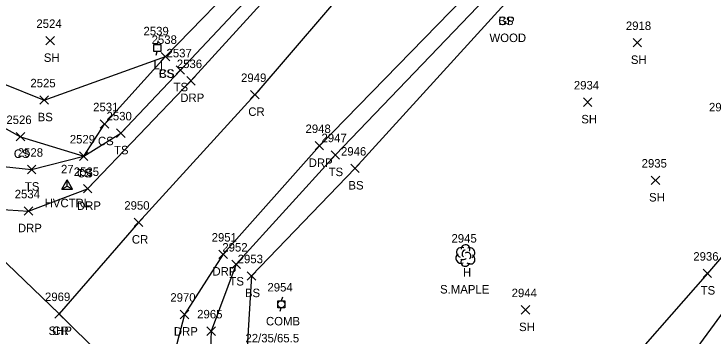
# Model space of a CAD drawing. Extents: x 1472233 to 1475777, y 540726 to 543442.
# Drawn here: x 1473841.3 to 1474005.9, y 542446.8 to 542522.7 of the extents above; entities that cross this region are included whole.
import ezdxf

# ---------------------------------------------------------------- set-up
doc = ezdxf.new("R2010")
doc.units = 0
for name, color, linetype in [('C_A', 7, 'Continuous'), ('C_I', 7, 'Continuous'), ('CPSM', 7, 'Continuous'), ('L_A', 7, 'Continuous'), ('L_C', 7, 'Continuous'), ('L_I', 7, 'Continuous'), ('L_TIC', 7, 'Continuous'), ('LELB', 7, 'Continuous'), ('LTD', 7, 'Continuous'), ('P_A', 7, 'Continuous'), ('P_I', 7, 'Continuous'), ('P_TIC', 7, 'Continuous'), ('PRC', 7, 'Continuous'), ('PSP', 7, 'Continuous'), ('R_A', 7, 'Continuous'), ('R_C', 7, 'Continuous'), ('R_I', 7, 'Continuous'), ('R_TIC', 7, 'Continuous'), ('RDP', 7, 'Continuous'), ('U_A', 7, 'Continuous'), ('U_C', 7, 'Continuous'), ('U_I', 7, 'Continuous'), ('ULP', 7, 'Continuous'), ('UP', 7, 'Continuous')]:
    doc.layers.add(name, color=color, linetype=linetype)

msp = doc.modelspace()

# ---------------------------------------------------------------- linework, layer by layer
at = {"layer": 'CPSM'}
for p, q in [((1473852.58, 542481.43), (1473853.83, 542483.59)), ((1473855.08, 542481.43), (1473853.83, 542483.59)), ((1473853.83, 542482.15), (1473853.83, 542483.59)), ((1473852.58, 542481.43), (1473853.83, 542482.15)), ((1473852.58, 542481.43), (1473855.08, 542481.43)), ((1473853.83, 542482.15), (1473853.83, 542482.15)), ((1473853.83, 542482.15), (1473855.08, 542481.43))]:
    msp.add_line(p, q, dxfattribs=at)
at = {"layer": 'L_TIC'}
for points in [[(1473848.84, 542515.42), (1473850.84, 542517.42)], [(1473850.84, 542515.42), (1473848.84, 542517.42)], [(1473987.03, 542514.93), (1473989.03, 542516.93)], [(1473989.03, 542514.93), (1473987.03, 542516.93)], [(1473875.97, 542511.66), (1473877.97, 542513.66)], [(1473877.97, 542511.66), (1473875.97, 542513.66)], [(1473875.97, 542511.66), (1473877.97, 542513.66)], [(1473877.97, 542511.66), (1473875.97, 542513.66)], [(1473879.47, 542508.49), (1473881.47, 542510.49)], [(1473881.47, 542508.49), (1473879.47, 542510.49)], [(1473847.43, 542501.42), (1473849.43, 542503.42)], [(1473849.43, 542501.42), (1473847.43, 542503.42)], [(1473975.36, 542500.92), (1473977.36, 542502.92)], [(1473977.36, 542500.92), (1473975.36, 542502.92)], [(1473861.63, 542495.77), (1473863.63, 542497.77)], [(1473863.63, 542495.77), (1473861.63, 542497.77)], [(1473865.44, 542493.63), (1473867.44, 542495.63)], [(1473867.44, 542493.63), (1473865.44, 542495.63)], [(1473841.83, 542492.77), (1473843.83, 542494.77)], [(1473843.83, 542492.77), (1473841.83, 542494.77)], [(1473856.71, 542488.19), (1473858.71, 542490.19)], [(1473858.71, 542488.19), (1473856.71, 542490.19)], [(1473856.71, 542488.19), (1473858.71, 542490.19)], [(1473858.71, 542488.19), (1473856.71, 542490.19)], [(1473915.95, 542488.49), (1473917.95, 542490.49)], [(1473917.95, 542488.49), (1473915.95, 542490.49)], [(1473920.59, 542485.33), (1473922.59, 542487.33)], [(1473922.59, 542485.33), (1473920.59, 542487.33)], [(1473844.46, 542485.06), (1473846.46, 542487.06)], [(1473846.46, 542485.06), (1473844.46, 542487.06)], [(1473991.31, 542482.51), (1473993.31, 542484.51)], [(1473993.31, 542482.51), (1473991.31, 542484.51)], [(1473892.61, 542462.71), (1473894.61, 542464.71)], [(1473894.61, 542462.71), (1473892.61, 542464.71)], [(1473896.23, 542459.96), (1473898.23, 542461.96)], [(1473898.23, 542459.96), (1473896.23, 542461.96)], [(1474003.53, 542460.57), (1474005.53, 542462.57)], [(1474005.53, 542460.57), (1474003.53, 542462.57)], [(1473960.71, 542451.96), (1473962.71, 542453.96)], [(1473962.71, 542451.96), (1473960.71, 542453.96)], [(1473886.74, 542446.96), (1473888.74, 542448.96)], [(1473888.74, 542446.96), (1473886.74, 542448.96)]]:
    msp.add_lwpolyline(points, dxfattribs=at)
at = {"layer": 'LELB'}
for points in [[(1473518.4, 542790.01), (1473563.89, 542744.47), (1473596.86, 542712.19), (1473621.23, 542688.95), (1473660.33, 542651.88), (1473689.02, 542624.42), (1473715.73, 542598.61), (1473746.44, 542571.32), (1473784.75, 542534.69), (1473817.99, 542514.69), (1473848.43, 542502.42), (1473876.97, 542512.66), (1473897.43, 542533.79), (1473923.6, 542558.96), (1473938.44, 542588.81), (1473927.53, 542599.64)], [(1473514.27, 542786.32), (1473560.24, 542740.99), (1473594.17, 542708.93), (1473617.93, 542685.84), (1473656.3, 542648.39), (1473686.09, 542620.25), (1473711.9, 542594.5), (1473742.08, 542567.84), (1473780.05, 542529.89), (1473807.97, 542506.72), (1473829.24, 542487.77), (1473845.46, 542486.06), (1473857.71, 542489.19), (1473866.44, 542494.63), (1473880.47, 542509.49), (1473900.34, 542530.71), (1473925.82, 542557.03), (1473946.47, 542580.98), (1473946.59, 542594.08), (1473931.4, 542613.43), (1473912.61, 542619.34)], [(1474165.95, 542731.94), (1474157.14, 542683.61), (1474148.57, 542649.89), (1474143.29, 542635.5), (1474139.19, 542631.93), (1474131.36, 542636.12), (1474120.53, 542648.69), (1474108.56, 542670.06), (1474101.39, 542688.23), (1474095.89, 542684.64), (1474093.95, 542684.48), (1474093.45, 542683.67), (1474093.16, 542677.96), (1474112.56, 542649.15), (1474130.63, 542628.83), (1474135.77, 542616.46), (1474134.45, 542606.68), (1474129.24, 542593.89), (1474099.76, 542548.63), (1474087.76, 542535.06), (1474054.57, 542501.68), (1474028.74, 542469.85), (1474011.69, 542457.24), (1473991.56, 542429.6)], [(1474090.14, 542675.56), (1474109.18, 542645.42), (1474125.12, 542625.07), (1474129.54, 542610.53), (1474116.17, 542580.79), (1474095.87, 542551.75), (1474082.52, 542541.7), (1474047.4, 542508.8), (1474023.57, 542483.66), (1474004.53, 542461.57), (1473981.42, 542435.1), (1473957.61, 542405.93), (1473949.71, 542379.54)], [(1474011.53, 542544.93), (1473997.92, 542550.92), (1473986.64, 542551.14), (1473974.36, 542545.99), (1473954.07, 542528.34), (1473916.95, 542489.49), (1473893.61, 542463.71), (1473887.74, 542447.96), (1473887.15, 542433.61)], [(1474038.07, 542519.87), (1474008.75, 542541.19), (1473994.7, 542544.04), (1473978.76, 542543.22), (1473956.88, 542525.09), (1473921.59, 542486.33), (1473897.23, 542460.96), (1473895.8, 542437.81), (1473900.03, 542423.77), (1473906.31, 542415.11), (1473930.79, 542395.25), (1473949.71, 542379.54), (1473992.28, 542347.15), (1474032.15, 542310.9), (1474067.46, 542281.43), (1474108.17, 542240.59), (1474125.43, 542226.08)], [(1473784.75, 542534.69), (1473812.87, 542510.45), (1473842.83, 542493.77), (1473857.71, 542489.19), (1473862.63, 542496.77), (1473876.97, 542512.66)]]:
    msp.add_lwpolyline(points, dxfattribs=at)
at = {"layer": 'LTD'}
msp.add_line((1473947.55, 542465.82), (1473947.55, 542465.82), dxfattribs=at)
msp.add_line((1473947.55, 542465.82), (1473947.55, 542465.82), dxfattribs=at)
msp.add_arc((1473947.59, 542467.26), 1.05, 335.5272, 180.9563, dxfattribs=at)
for centre, major_axis, ratio, start_param, end_param in [((1473946.76, 542466.49), (1.21, -0.51), 0.895232, 1.570796, 4.712389), ((1473948.59, 542466.41), (-1.14, -0.48), 0.949671, 1.570796, 4.712389), ((1473946.46, 542465.12), (0.58, -1.04), 0.959034, 3.141593, 6.283185), ((1473947.34, 542466.28), (-0.208, -0.792), 0.645439, 3.141593, 6.283185), ((1473948.05, 542465.66), (-0.5, 0.667), 0.989748, 3.141593, 6.283185), ((1473947.55, 542464.32), (0.26, 1.06), 0.942809, 1.570796, 4.712389), ((1473947.09, 542465.07), (-0.625, -0.083), 0.423636, 0, 3.141593), ((1473948.55, 542464.99), (-1.09, 0.79), 0.841452, 1.570796, 4.712389)]:
    msp.add_ellipse(centre, major_axis=major_axis, ratio=ratio, start_param=start_param, end_param=end_param, dxfattribs=at)
at = {"layer": 'P_TIC'}
for points in [[(1473897.02, 542502.68), (1473899.02, 542504.68)], [(1473899.02, 542502.68), (1473897.02, 542504.68)], [(1473869.62, 542472.58), (1473871.62, 542474.58)], [(1473871.62, 542472.58), (1473869.62, 542474.58)], [(1473850.91, 542451.04), (1473852.91, 542453.04)], [(1473852.91, 542451.04), (1473850.91, 542453.04)], [(1473850.91, 542451.04), (1473852.91, 542453.04)], [(1473852.91, 542451.04), (1473850.91, 542453.04)]]:
    msp.add_lwpolyline(points, dxfattribs=at)
at = {"layer": 'PRC'}
msp.add_lwpolyline([(1474124.73, 542867.45), (1474138.24, 542842.57), (1474146.26, 542814.27), (1474147.99, 542793.2), (1474140.2, 542767.69), (1474131.39, 542751.59), (1474113.96, 542729.51), (1474092.05, 542706.63), (1474043.97, 542656.44), (1473995.22, 542610.58), (1473969.45, 542582.1), (1473923.18, 542533.15), (1473898.02, 542503.68), (1473870.62, 542473.58), (1473851.91, 542452.04)], dxfattribs=at)
at = {"layer": 'PSP'}
msp.add_lwpolyline([(1473511.53, 542783.65), (1473557.71, 542738.52), (1473591.71, 542705.85), (1473614.8, 542682.52), (1473653.25, 542645.69), (1473682.39, 542616.78), (1473708.77, 542591.71), (1473737.42, 542563.39), (1473776.1, 542525.9), (1473801.03, 542501.12), (1473821.16, 542481.55), (1473851.91, 542452.04), (1473882.06, 542422.12), (1473920.54, 542384.18), (1473958.97, 542346.58), (1473974.8, 542332.02), (1474016, 542291.37), (1474048.58, 542260.06), (1474087.68, 542221.94), (1474123.03, 542187.8), (1474161.37, 542151.41), (1474230.43, 542083.96), (1474265.44, 542049.86)], dxfattribs=at)
at = {"layer": 'R_TIC'}
for points in [[(1473881.96, 542505.96), (1473883.96, 542507.96)], [(1473883.96, 542505.96), (1473881.96, 542507.96)], [(1473912.19, 542490.65), (1473914.19, 542492.65)], [(1473914.19, 542490.65), (1473912.19, 542492.65)], [(1473857.64, 542480.53), (1473859.64, 542482.53)], [(1473859.64, 542480.53), (1473857.64, 542482.53)], [(1473843.74, 542475.26), (1473845.74, 542477.26)], [(1473845.74, 542475.26), (1473843.74, 542477.26)], [(1473889.53, 542465.06), (1473891.53, 542467.06)], [(1473891.53, 542465.06), (1473889.53, 542467.06)], [(1473880.45, 542450.89), (1473882.45, 542452.89)], [(1473882.45, 542450.89), (1473880.45, 542452.89)]]:
    msp.add_lwpolyline(points, dxfattribs=at)
at = {"layer": 'RDP'}
for points in [[(1474156.9, 542816.07), (1474158.25, 542792.55), (1474149.71, 542763.53), (1474141.06, 542745.97), (1474122.05, 542721.57), (1474099.16, 542696.92), (1474072.3, 542669.38), (1474064.97, 542659.15), (1474064.16, 542645.99), (1474070.96, 542633.45), (1474104.89, 542594.5), (1474067.57, 542556.96), (1474038.11, 542526.02), (1474001.11, 542557.22), (1473988.17, 542557.88), (1473978.19, 542554.56), (1473968.9, 542548.06), (1473950.18, 542529.64), (1473913.19, 542491.65), (1473890.53, 542466.06), (1473881.45, 542451.89), (1473878.79, 542441.67), (1473879.57, 542429.36), (1473882.06, 542422.12)], [(1473821.16, 542481.55), (1473834.93, 542476.88), (1473844.74, 542476.26), (1473858.64, 542481.53), (1473882.96, 542506.96), (1473902.65, 542528.64), (1473928.15, 542555.41), (1473950.59, 542578.52), (1473956.71, 542587.39), (1473958.08, 542597.85), (1473945.85, 542612.63), (1473922.1, 542634.86), (1473922.68, 542635.63), (1473934.21, 542647.92)]]:
    msp.add_lwpolyline(points, dxfattribs=at)
at = {"layer": 'ULP'}
for p, q in [((1473874.22, 542513.85), (1473874.22, 542515.51)), ((1473874.22, 542515.51), (1473875.89, 542515.51)), ((1473875.22, 542516.35), (1473875.05, 542515.51)), ((1473875.89, 542515.51), (1473875.89, 542513.85)), ((1473875.89, 542513.85), (1473874.22, 542513.85)), ((1473874.8, 542513.01), (1473875.05, 542513.85)), ((1473875.05, 542514.68), (1473875.05, 542514.68))]:
    msp.add_line(p, q, dxfattribs=at)
at = {"layer": 'UP'}
for p, q in [((1473903.4, 542453.47), (1473903.4, 542455.13)), ((1473903.4, 542455.13), (1473905.07, 542455.13)), ((1473904.48, 542455.97), (1473904.23, 542455.13)), ((1473905.07, 542455.13), (1473905.07, 542453.47)), ((1473905.07, 542453.47), (1473903.4, 542453.47)), ((1473903.98, 542452.63), (1473904.23, 542453.47)), ((1473904.23, 542454.3), (1473904.23, 542454.3))]:
    msp.add_line(p, q, dxfattribs=at)
msp.add_circle((1473904.23, 542454.3), 0.833, dxfattribs=at)

# ---------------------------------------------------------------- texts
at = {"layer": 'C_A'}
msp.add_text('HVCTRL', height=2, dxfattribs=at).set_placement((1473848.52, 542477.15))
at = {"layer": 'C_I'}
msp.add_text('27', height=2, dxfattribs=at).set_placement((1473852.37, 542485.15))
at = {"layer": 'L_A'}
for s, p in [('BS', (1473955.32, 542520.09)), ('SH', (1473848.33, 542511.42)), ('SH', (1473986.52, 542510.93)), ('CS', (1473875.41, 542507.66)), ('BS', (1473875.41, 542507.66)), ('TS', (1473878.87, 542504.49)), ('BS', (1473846.88, 542497.42)), ('SH', (1473974.85, 542496.92)), ('CS', (1473861.07, 542491.77)), ('CS', (1473841.27, 542488.77)), ('TS', (1473864.85, 542489.63)), ('TS', (1473856.12, 542484.19)), ('CS', (1473856.15, 542484.19)), ('TS', (1473915.36, 542484.49)), ('TS', (1473843.87, 542481.06)), ('BS', (1473920.03, 542481.33)), ('SH', (1473990.8, 542478.51)), ('H', (1473946.98, 542460.82)), ('TS', (1473892.02, 542458.71)), ('BS', (1473895.67, 542455.96)), ('TS', (1474002.94, 542456.57)), ('SH', (1473960.2, 542447.96))]:
    msp.add_text(s, height=2, dxfattribs=at).set_placement(p)
at = {"layer": 'L_C'}
msp.add_text('S.MAPLE', height=2, dxfattribs=at).set_placement((1473941.61, 542456.82))
at = {"layer": 'L_I'}
for s, p in [('2524', (1473846.58, 542519.42)), ('2918', (1473985.34, 542518.93)), ('2538', (1473873.71, 542515.66)), ('2538', (1473873.71, 542515.66)), ('2537', (1473877.21, 542512.49)), ('2525', (1473845.17, 542505.42)), ('2934', (1473973.1, 542504.92)), ('2531', (1473859.94, 542499.77)), ('2917', (1474004.9, 542499.75)), ('2530', (1473863.09, 542497.63)), ('2526', (1473839.52, 542496.77)), ('2529', (1473854.44, 542492.19)), ('2529', (1473854.44, 542492.19)), ('2947', (1473913.69, 542492.49)), ('2528', (1473842.2, 542489.06)), ('2946', (1473918.28, 542489.33)), ('2935', (1473989.05, 542486.51)), ('2945', (1473944.29, 542468.82)), ('2952', (1473890.35, 542466.71)), ('2953', (1473893.97, 542463.96)), ('2936', (1474001.21, 542464.57)), ('2944', (1473958.45, 542455.96)), ('2965', (1473884.43, 542450.96))]:
    msp.add_text(s, height=2, dxfattribs=at).set_placement(p)
at = {"layer": 'P_A'}
for s, p in [('CR', (1473896.46, 542498.68)), ('CR', (1473869.05, 542468.58)), ('SHP', (1473849.45, 542447.04)), ('CR', (1473850.34, 542447.04))]:
    msp.add_text(s, height=2, dxfattribs=at).set_placement(p)
at = {"layer": 'P_I'}
for s, p in [('2949', (1473894.76, 542506.68)), ('2950', (1473867.27, 542476.58)), ('2969', (1473848.6, 542455.04)), ('2969', (1473848.6, 542455.04))]:
    msp.add_text(s, height=2, dxfattribs=at).set_placement(p)
at = {"layer": 'R_A'}
for s, p in [('GP', (1473955.31, 542520.09)), ('DRP', (1473880.45, 542501.96)), ('DRP', (1473910.68, 542486.65)), ('DRP', (1473856.13, 542476.53)), ('DRP', (1473842.23, 542471.26)), ('DRP', (1473888.02, 542461.06)), ('DRP', (1473878.94, 542446.89))]:
    msp.add_text(s, height=2, dxfattribs=at).set_placement(p)
at = {"layer": 'R_C'}
msp.add_text('WOOD', height=2, dxfattribs=at).set_placement((1473953.24, 542516.09))
at = {"layer": 'R_I'}
for s, p in [('2536', (1473879.64, 542509.96)), ('2948', (1473909.93, 542494.65)), ('2535', (1473855.38, 542484.53)), ('2534', (1473841.48, 542479.26)), ('2951', (1473887.84, 542469.06)), ('2970', (1473878.11, 542454.89))]:
    msp.add_text(s, height=2, dxfattribs=at).set_placement(p)
at = {"layer": 'U_A'}
for s, p in [('LI', (1473874.16, 542509.68)), ('COMB', (1473900.62, 542449.3))]:
    msp.add_text(s, height=2, dxfattribs=at).set_placement(p)
at = {"layer": 'U_C'}
msp.add_text('22/35/65.5', height=2, dxfattribs=at).set_placement((1473895.79, 542445.3))
at = {"layer": 'U_I'}
for s, p in [('2539', (1473871.79, 542517.68)), ('2954', (1473900.97, 542457.3))]:
    msp.add_text(s, height=2, dxfattribs=at).set_placement(p)

doc.saveas('drawing.dxf')
